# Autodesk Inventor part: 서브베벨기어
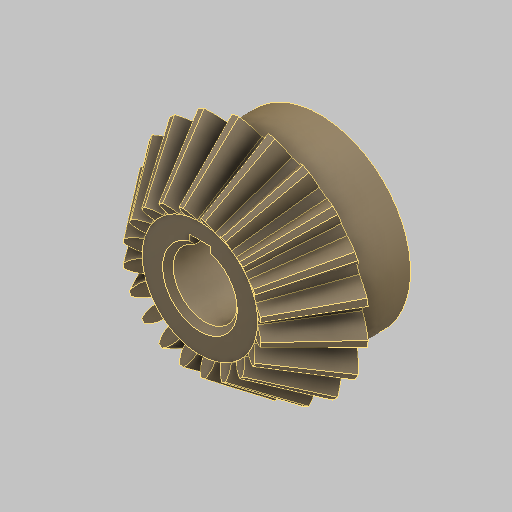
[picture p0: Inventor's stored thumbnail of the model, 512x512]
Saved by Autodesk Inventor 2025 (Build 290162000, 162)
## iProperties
Created: 2024-08
Part Number: 서브베벨기어
Material: 강철, 탄소
Document SubType Name: Modeling
Designer: 현기
Density: 7.87 g/cm^3
Appearance: 기본값
Author: jhkim
Sending System: Autodesk Inventor 2025
Preprocessor: ST-DEVELOPER v20
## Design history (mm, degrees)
node "복구된 형상1"
  node "스케치11"
feature "Solid1"
node "스케치10"
node "솔리드1"
